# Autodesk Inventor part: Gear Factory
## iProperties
Author: Administrator
Shininess: 25.0
PropertySet Name: _Private Model Information
Length Units: 11272
Angle Units: 11286
Time Units: 11279
Mass Units: 11290
Length Display Precision: 3
Angle Display Precision: 2
Compacted: False
Created: 2000-11
Part Number: Gear Factory
Document SubType Name: Modeling
Designer: Administrator
Control State: 0
Master: False
Checked Out: False
PropertySet Name: Design Tracking Control
Density: 0.0
Volumn: 0.0
Area: 0.0
PropertySet Name: Model Information
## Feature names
1. Extrusion1
2. Circular Pattern1
3. Extrusion2
4. Extrusion3
5. Extrusion4
6. Extrusion5
7. Extrusion6
8. Extrusion7
